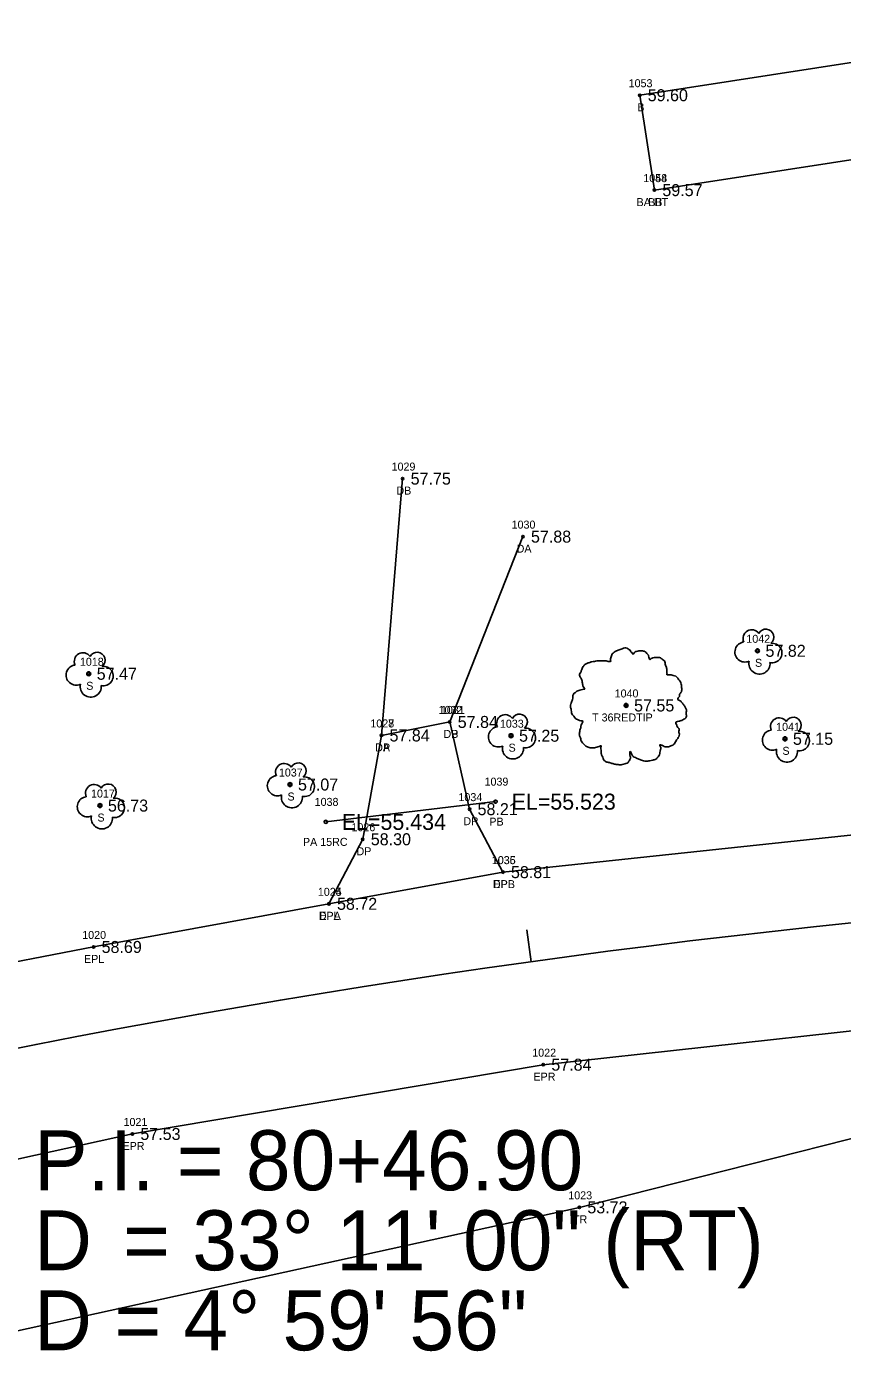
# Model space of a CAD drawing. Extents: x 2420113 to 2422887, y 845323 to 846653.
# Drawn here: x 2420428.1 to 2420530, y 845663.8 to 845830.4 of the extents above; entities that cross this region are included whole.
import ezdxf

# ---------------------------------------------------------------- set-up
doc = ezdxf.new("R2010")
doc.units = 0
for name, color, linetype in [('RD_EX_Bldg', 7, 'Continuous'), ('RD_EX_Bldg_txCode', 7, 'Continuous'), ('RD_EX_DR_Pipe', 7, 'Continuous'), ('RD_EX_DR_Pipe_txCode', 7, 'Continuous'), ('RD_EX_Driveway', 7, 'Continuous'), ('RD_EX_Driveway_txCode', 7, 'Continuous'), ('RD_EX_Road', 7, 'Continuous'), ('RD_EX_Road_txCode', 7, 'Continuous'), ('RD_EX_TX_Bldg_ELEV', 7, 'Continuous'), ('RD_EX_TX_Driveway_ELEV', 7, 'Continuous'), ('RD_EX_TX_Road_ELEV', 7, 'Continuous'), ('RD_EX_TX_VEG_ELEV', 7, 'Continuous'), ('RD_EX_VEG', 7, 'Continuous'), ('RD_EX_VEG_txCode', 7, 'Continuous'), ('RD_HC_Cl', 7, 'Continuous'), ('RD_HC_Data', 7, 'Continuous'), ('RD_HC_Data_Tic', 7, 'Continuous'), ('RD_SMD_Locator', 7, 'Continuous'), ('RD_TX_Pipe_ElevEX', 7, 'Continuous')]:
    doc.layers.add(name, color=color, linetype=linetype)

msp = doc.modelspace()

# ---------------------------------------------------------------- linework, layer by layer
at = {"layer": 'RD_EX_Bldg'}
msp.add_lwpolyline([(2420506.49, 845809.99), (2420562.05, 845818.56), (2420560.22, 845830.42), (2420504.66, 845821.85), (2420506.49, 845809.99)], dxfattribs=at)
at = {"layer": 'RD_EX_DR_Pipe'}
msp.add_line((2420465.45, 845731.04), (2420486.66, 845733.57), dxfattribs=at)
at = {"layer": 'RD_EX_Driveway'}
for p, q in [((2420472.41, 845741.84), (2420475.05, 845773.94)), ((2420490.08, 845766.69), (2420480.93, 845743.53))]:
    msp.add_line(p, q, dxfattribs=at)
msp.add_lwpolyline([(2420465.85, 845720.8), (2420470.07, 845728.87), (2420472.41, 845741.84), (2420480.93, 845743.53), (2420483.41, 845732.63), (2420487.58, 845724.76)], dxfattribs=at)
at = {"layer": 'RD_EX_Road'}
for points in [[(2420388.28, 845680.39), (2420441.29, 845692.04), (2420492.62, 845700.7), (2420553.92, 845707.41), (2420607.69, 845710.85), (2420682.38, 845711.26), (2420749.44, 845707.27), (2420795.12, 845703.44), (2420900.28, 845693.42), (2421017.17, 845682.19), (2421113.9, 845672.97), (2421174.87, 845668.16), (2421234.59, 845666.13), (2421293, 845667.25), (2421351.24, 845671.5), (2421419.82, 845681.17), (2421463.19, 845688.63), (2421558.82, 845713.18), (2421614.57, 845730.45), (2421670.73, 845751.42), (2421735.61, 845780.5), (2421750.75, 845787.87), (2421744.67, 845798.22), (2421739.21, 845808.11)], [(2420376.35, 845701.93), (2420403.68, 845709.11), (2420436.45, 845715.41), (2420465.85, 845720.8), (2420487.58, 845724.76), (2420551.29, 845731.53), (2420607.05, 845734.89), (2420658.72, 845735.59), (2420682.86, 845735.47), (2420736.67, 845732.56), (2420795.4, 845727.65), (2420889.7, 845718.98), (2420911.08, 845716.87), (2420953.91, 845713.71), (2420998.34, 845708.25), (2421018.47, 845706.55), (2421116.02, 845696.98), (2421176.98, 845692), (2421235.85, 845690.14), (2421292.32, 845691.44), (2421350.22, 845695.49), (2421412.35, 845704.28)]]:
    msp.add_lwpolyline(points, dxfattribs=at)
at = {"layer": 'RD_EX_VEG'}
msp.add_lwpolyline([(2420391.44, 845659.63), (2420497.12, 845682.87), (2420554.96, 845697.51), (2420665.26, 845702.88), (2420735.64, 845697.65), (2420790.66, 845674.79), (2421018.22, 845655.05), (2421176.12, 845636.22), (2421296.76, 845636.57), (2421411.61, 845653.11), (2421415.24, 845569.55)], dxfattribs=at)
for centre, radius in [((2420519.37, 845752.42), 0.25), ((2420435.84, 845749.55), 0.25), ((2420502.96, 845745.59), 0.25), ((2420502.94, 845745.57), 0.0001), ((2420488.59, 845741.81), 0.25), ((2420522.8, 845741.42), 0.25), ((2420460.98, 845735.71), 0.25), ((2420437.24, 845733.08), 0.25)]:
    msp.add_circle(centre, radius, dxfattribs=at)
for centre, radius, start, end in [((2420518.65, 845753.97), 1.08, 34.9763, 204.756), ((2420520.41, 845754.13), 0.995, 308.7626, 152.0467), ((2420517.81, 845752.27), 1.26, 96.4518, 294.734), ((2420521.21, 845752.14), 1.22, 256.5667, 98.1046), ((2420435.12, 845751.1), 1.08, 34.9763, 204.756), ((2420436.89, 845751.25), 0.995, 308.7626, 152.0467), ((2420434.28, 845749.39), 1.26, 96.4518, 294.734), ((2420437.68, 845749.27), 1.22, 256.5667, 98.1046), ((2420519.62, 845750.83), 1.32, 166.8827, 5.7589), ((2420436.09, 845747.95), 1.32, 166.8827, 5.7589), ((2420487.87, 845743.36), 1.08, 34.9763, 204.756), ((2420489.63, 845743.51), 0.995, 308.7626, 152.0467), ((2420522.08, 845742.96), 1.08, 34.9763, 204.756), ((2420523.85, 845743.12), 0.995, 308.7626, 152.0467), ((2420487.02, 845741.66), 1.26, 96.4518, 294.734), ((2420490.43, 845741.53), 1.22, 256.5667, 98.1046), ((2420521.24, 845741.26), 1.26, 96.4518, 294.734), ((2420524.64, 845741.14), 1.22, 256.5667, 98.1046), ((2420488.83, 845740.22), 1.32, 166.8827, 5.7589), ((2420523.05, 845739.82), 1.32, 166.8827, 5.7589), ((2420460.26, 845737.26), 1.08, 34.9763, 204.756), ((2420462.02, 845737.42), 0.995, 308.7626, 152.0467), ((2420459.41, 845735.56), 1.26, 96.4518, 294.734), ((2420462.82, 845735.43), 1.22, 256.5667, 98.1046), ((2420436.52, 845734.63), 1.08, 34.9763, 204.756), ((2420438.28, 845734.78), 0.995, 308.7626, 152.0467), ((2420435.67, 845732.93), 1.26, 96.4518, 294.734), ((2420439.08, 845732.8), 1.22, 256.5667, 98.1046), ((2420461.22, 845734.12), 1.32, 166.8827, 5.7589), ((2420437.48, 845731.48), 1.32, 166.8827, 5.7589)]:
    msp.add_arc(centre, radius, start, end, dxfattribs=at)
for points in [[(2420503.09, 845752.75), (2420502.79, 845752.78), (2420502.46, 845752.68), (2420502.21, 845752.58), (2420501.99, 845752.5), (2420501.76, 845752.4), (2420501.47, 845752.23), (2420501.24, 845752.03), (2420501.12, 845751.78), (2420501.07, 845751.55), (2420501.02, 845751.28), (2420501.02, 845751.1), (2420500.89, 845751.08), (2420500.74, 845751.1), (2420500.49, 845751.18), (2420500.24, 845751.18), (2420499.99, 845751.18), (2420499.64, 845751.15), (2420499.29, 845751.15), (2420499.02, 845751.1), (2420498.69, 845751.05), (2420498.32, 845750.93), (2420497.97, 845750.8), (2420497.67, 845750.55), (2420497.42, 845750.08), (2420497.29, 845749.73), (2420497.14, 845749.48), (2420497.29, 845749.03), (2420497.47, 845748.68), (2420497.49, 845748.48), (2420497.57, 845748.06), (2420497.67, 845747.83), (2420497.79, 845747.63), (2420497.72, 845747.61), (2420497.34, 845747.56), (2420497.04, 845747.46), (2420496.62, 845747.23), (2420496.39, 845747.01), (2420496.29, 845746.68), (2420496.27, 845746.33), (2420496.17, 845746.13), (2420496.09, 845745.86), (2420496.07, 845745.78), (2420496.02, 845745.46), (2420496.12, 845745.01), (2420496.14, 845744.66), (2420496.27, 845744.43), (2420496.42, 845744.26), (2420496.59, 845744.01), (2420496.99, 845743.78), (2420497.32, 845743.68), (2420497.52, 845743.66), (2420497.34, 845743.16), (2420497.29, 845742.81), (2420497.17, 845742.41), (2420497.17, 845742.33), (2420497.12, 845741.86), (2420497.27, 845741.53), (2420497.34, 845741.16), (2420497.52, 845740.93), (2420497.79, 845740.63), (2420498.12, 845740.41), (2420498.62, 845740.28), (2420499.02, 845740.31), (2420499.59, 845740.48), (2420499.84, 845740.56), (2420499.82, 845740.38), (2420499.84, 845740.01), (2420499.84, 845739.58), (2420499.99, 845739.26), (2420500.09, 845738.98), (2420500.24, 845738.73), (2420500.57, 845738.51), (2420500.97, 845738.43), (2420501.39, 845738.28), (2420501.84, 845738.21), (2420502.34, 845738.18), (2420502.94, 845738.33), (2420503.21, 845738.46), (2420503.31, 845738.63), (2420503.51, 845739.01), (2420503.46, 845739.23), (2420503.49, 845739.83), (2420503.59, 845739.66), (2420503.76, 845739.31), (2420504.26, 845739.01), (2420504.66, 845738.83), (2420505.14, 845738.68), (2420505.44, 845738.61), (2420505.91, 845738.68), (2420506.29, 845738.76), (2420506.66, 845738.88), (2420506.96, 845739.16), (2420507.14, 845739.43), (2420507.19, 845739.71), (2420507.26, 845740.08), (2420507.31, 845740.26)], [(2420507.31, 845740.26), (2420507.24, 845740.43), (2420507.19, 845740.68), (2420507.26, 845740.66), (2420507.44, 845740.61), (2420507.71, 845740.48), (2420507.94, 845740.41), (2420508.26, 845740.43), (2420508.54, 845740.53), (2420508.99, 845740.81), (2420509.26, 845741.28), (2420509.54, 845741.68), (2420509.61, 845742.01), (2420509.56, 845742.23), (2420509.54, 845742.73), (2420509.34, 845742.98), (2420509.29, 845743.11), (2420509.19, 845743.51), (2420509.26, 845743.56), (2420509.54, 845743.61), (2420509.91, 845743.73), (2420510.19, 845743.86), (2420510.41, 845744.03), (2420510.49, 845744.26), (2420510.46, 845744.66), (2420510.51, 845745.06), (2420510.44, 845745.21), (2420510.34, 845745.36), (2420510.26, 845745.56), (2420510.11, 845745.71), (2420510.01, 845745.86), (2420509.91, 845745.96), (2420509.79, 845746.11), (2420509.61, 845746.23), (2420509.46, 845746.28), (2420509.41, 845746.43), (2420509.56, 845746.63), (2420509.61, 845746.73), (2420509.64, 845746.96), (2420509.86, 845747.31), (2420509.91, 845747.71), (2420509.86, 845748.13), (2420509.81, 845748.4), (2420509.66, 845748.68), (2420509.46, 845748.93), (2420509.34, 845749.1), (2420509.16, 845749.23), (2420508.84, 845749.35), (2420508.59, 845749.4), (2420508.24, 845749.4), (2420508.04, 845749.45), (2420508.06, 845749.5), (2420508.06, 845749.65), (2420508.06, 845749.93), (2420507.99, 845750.38), (2420507.84, 845750.88), (2420507.84, 845750.9), (2420507.74, 845751.15), (2420507.51, 845751.35), (2420507.34, 845751.45), (2420507.14, 845751.58), (2420506.89, 845751.6), (2420506.59, 845751.6), (2420506.31, 845751.55), (2420506.11, 845751.45), (2420505.94, 845751.33), (2420505.86, 845751.48), (2420505.76, 845751.78), (2420505.71, 845751.93), (2420505.56, 845752.1), (2420505.34, 845752.3), (2420504.89, 845752.43), (2420504.26, 845752.35), (2420503.96, 845752.15), (2420503.81, 845751.98), (2420503.76, 845752.1), (2420503.56, 845752.3), (2420503.46, 845752.48), (2420503.29, 845752.6), (2420503.14, 845752.7), (2420503.04, 845752.75)]]:
    msp.add_spline(points, degree=3, dxfattribs=at)
at = {"layer": 'RD_HC_Cl'}
msp.add_arc((2420649.07, 844578.36), 1146.15, 84.46476, 117.6481, dxfattribs=at)
at = {"layer": 'RD_HC_Data_Tic'}
msp.add_line((2420491.1, 845713.56), (2420490.55, 845717.53), dxfattribs=at)
at = {"layer": 'RD_SMD_Locator'}
for centre, radius in [((2420504.66, 845821.85), 0.15), ((2420506.49, 845809.99), 0.15), ((2420506.49, 845809.99), 0.15), ((2420475.05, 845773.94), 0.15), ((2420490.08, 845766.69), 0.15), ((2420519.37, 845752.42), 0.15), ((2420435.84, 845749.55), 0.15), ((2420502.96, 845745.59), 0.15), ((2420480.93, 845743.53), 0.15), ((2420480.93, 845743.53), 0.15), ((2420472.41, 845741.84), 0.15), ((2420472.41, 845741.84), 0.15), ((2420488.59, 845741.81), 0.15), ((2420522.8, 845741.42), 0.15), ((2420460.98, 845735.71), 0.15), ((2420437.24, 845733.08), 0.15), ((2420486.66, 845733.57), 0.2), ((2420483.41, 845732.63), 0.15), ((2420465.45, 845731.04), 0.2), ((2420470.07, 845728.87), 0.15), ((2420487.58, 845724.76), 0.15), ((2420487.58, 845724.76), 0.15), ((2420465.85, 845720.8), 0.15), ((2420465.85, 845720.8), 0.15), ((2420436.45, 845715.41), 0.15), ((2420492.62, 845700.7), 0.15), ((2420441.29, 845692.04), 0.15), ((2420497.12, 845682.87), 0.15)]:
    msp.add_circle(centre, radius, dxfattribs=at)

# ---------------------------------------------------------------- texts
at = {"layer": 'RD_EX_Bldg_txCode'}
for s, p in [('1053', (2420503.28, 845822.85)), ('B', (2420504.36, 845819.85)), ('1048', (2420505.11, 845810.99)), ('1054', (2420505.11, 845810.99)), ('BA HT', (2420504.27, 845807.99)), ('BB', (2420505.71, 845807.99))]:
    msp.add_text(s, height=1, dxfattribs=at).set_placement(p)
at = {"layer": 'RD_EX_DR_Pipe_txCode'}
for s, p in [('1039', (2420485.28, 845735.57)), ('1038', (2420464.06, 845733.04)), ('PB', (2420485.88, 845730.57)), ('PA 15RC', (2420462.6, 845728.04))]:
    msp.add_text(s, height=1, dxfattribs=at).set_placement(p)
at = {"layer": 'RD_EX_Driveway_txCode'}
for s, p in [('1029', (2420473.67, 845774.94)), ('DB', (2420474.27, 845771.94)), ('1030', (2420488.66, 845767.69)), ('DA', (2420489.29, 845764.69)), ('1032', (2420479.54, 845744.53)), ('1031', (2420479.83, 845744.53)), ('1027', (2420471.02, 845742.84)), ('1028', (2420471.02, 845742.84)), ('DB', (2420480.15, 845741.53)), ('DP', (2420480.15, 845741.53)), ('DA', (2420471.61, 845739.84)), ('DP', (2420471.63, 845739.84)), ('1034', (2420482.02, 845733.63)), ('DP', (2420482.63, 845730.63)), ('1026', (2420468.66, 845729.87)), ('DP', (2420469.29, 845726.87)), ('1035', (2420486.2, 845725.76)), ('DPB', (2420486.33, 845722.76)), ('1025', (2420464.46, 845721.8)), ('DPA', (2420464.58, 845718.8))]:
    msp.add_text(s, height=1, dxfattribs=at).set_placement(p)
at = {"layer": 'RD_EX_Road_txCode'}
for s, p in [('1036', (2420486.18, 845725.76)), ('EPL', (2420486.38, 845722.76)), ('1024', (2420464.46, 845721.8)), ('EPL', (2420464.64, 845718.8)), ('1020', (2420435.03, 845716.41)), ('EPL', (2420435.25, 845713.41)), ('1022', (2420491.24, 845701.7)), ('EPR', (2420491.39, 845698.7)), ('1021', (2420440.19, 845693.04)), ('EPR', (2420440.06, 845690.04))]:
    msp.add_text(s, height=1, dxfattribs=at).set_placement(p)
at = {"layer": 'RD_EX_TX_Bldg_ELEV'}
for s, p in [('59.60', (2420505.66, 845821.1)), ('59.57', (2420507.49, 845809.24)), ('59.57', (2420507.49, 845809.24))]:
    msp.add_text(s, height=1.5, dxfattribs=at).set_placement(p)
at = {"layer": 'RD_EX_TX_Driveway_ELEV'}
for s, p in [('57.75', (2420476.05, 845773.19)), ('57.88', (2420491.08, 845765.94)), ('57.84', (2420481.93, 845742.78)), ('57.84', (2420481.93, 845742.78)), ('57.84', (2420473.41, 845741.09)), ('57.84', (2420473.41, 845741.09)), ('58.21', (2420484.41, 845731.88)), ('58.30', (2420471.07, 845728.12)), ('58.81', (2420488.58, 845724.01)), ('58.72', (2420466.85, 845720.05))]:
    msp.add_text(s, height=1.5, dxfattribs=at).set_placement(p)
at = {"layer": 'RD_EX_TX_Road_ELEV'}
for s, p in [('58.81', (2420488.58, 845724.01)), ('58.72', (2420466.85, 845720.05)), ('58.69', (2420437.45, 845714.66)), ('57.84', (2420493.62, 845699.95)), ('57.53', (2420442.29, 845691.29))]:
    msp.add_text(s, height=1.5, dxfattribs=at).set_placement(p)
at = {"layer": 'RD_EX_TX_VEG_ELEV'}
for s, p in [('57.82', (2420520.37, 845751.67)), ('57.47', (2420436.84, 845748.8)), ('57.55', (2420503.96, 845744.84)), ('57.25', (2420489.59, 845741.06)), ('57.15', (2420523.8, 845740.67)), ('57.07', (2420461.98, 845734.96)), ('56.73', (2420438.24, 845732.33)), ('53.73', (2420498.12, 845682.12))]:
    msp.add_text(s, height=1.5, dxfattribs=at).set_placement(p)
at = {"layer": 'RD_EX_VEG_txCode'}
for s, p in [('1042', (2420517.98, 845753.42)), ('1018', (2420434.74, 845750.55)), ('S', (2420519.06, 845750.42)), ('S', (2420435.53, 845747.55)), ('1040', (2420501.53, 845746.59)), ('1033', (2420487.2, 845742.81)), ('T 36REDTIP', (2420498.71, 845743.59)), ('1041', (2420521.7, 845742.42)), ('S', (2420488.28, 845739.81)), ('S', (2420522.49, 845739.42)), ('1037', (2420459.59, 845736.71)), ('1017', (2420436.13, 845734.08)), ('S', (2420460.67, 845733.71)), ('S', (2420436.93, 845731.08)), ('1023', (2420495.74, 845683.87)), ('TR', (2420496.33, 845680.87))]:
    msp.add_text(s, height=1, dxfattribs=at).set_placement(p)
at = {"layer": 'RD_HC_Data'}
for s, p in [('P.I. = 80+46.90', (2420429, 845685)), ('D', (2420429, 845675)), ('    = 33%%d 11\' 00" (RT)', (2420429, 845675)), ('D = 4%%d 59\' 56"', (2420429, 845665))]:
    msp.add_text(s, height=7.5, dxfattribs=at).set_placement(p)
at = {"layer": 'RD_TX_Pipe_ElevEX'}
for s, p in [('EL=55.523', (2420488.66, 845732.57)), ('EL=55.434', (2420467.45, 845730.04))]:
    msp.add_text(s, height=2, dxfattribs=at).set_placement(p)

doc.saveas('drawing.dxf')
